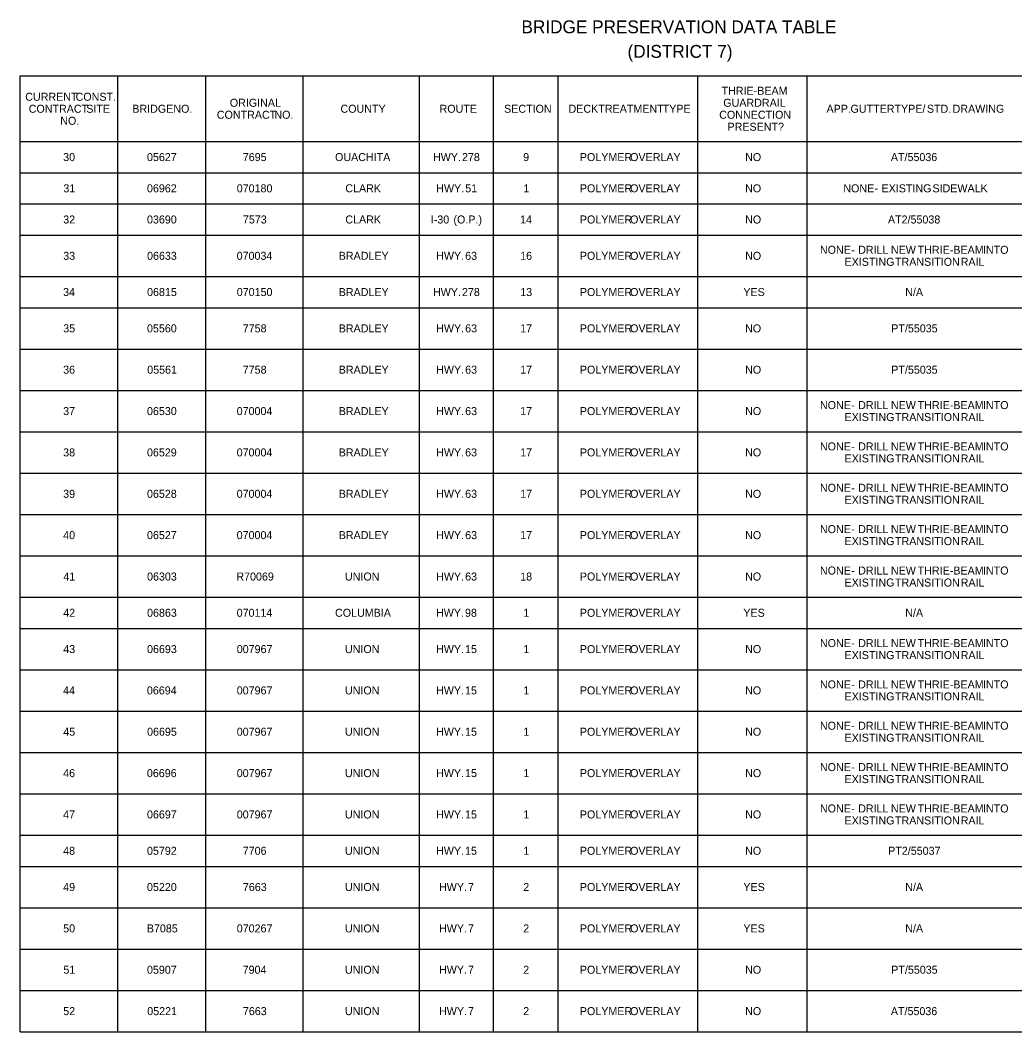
# Model space of a CAD drawing. Extents: x 16 to 1228740, y 11 to 152440.
# Drawn here: x 16.253 to 17.546, y 11.005 to 12.32 of the extents above; entities that cross this region are included whole.
import ezdxf

# ---------------------------------------------------------------- set-up
doc = ezdxf.new("R2010")
doc.units = 0
doc.layers.add('B_border', color=7, linetype='Continuous')
doc.layers.add('Default', color=7, linetype='Continuous')

msp = doc.modelspace()

# ---------------------------------------------------------------- linework, layer by layer
at = {"layer": 'B_border'}
msp.add_line((16.2529, 12.2472), (16.2529, 12.2472), dxfattribs=at)
at = {"layer": 'Default'}
for p, q in [((16.2529, 12.2472), (17.9726, 12.2472)), ((16.2529, 11.0051), (16.2529, 12.2472)), ((16.3796, 11.0051), (16.3796, 12.2472)), ((16.4942, 11.0051), (16.4942, 12.2472)), ((16.6209, 11.0051), (16.6209, 12.2472)), ((16.772, 11.0051), (16.772, 12.2472)), ((16.8684, 11.0051), (16.8684, 12.2472)), ((16.9525, 11.0051), (16.9525, 12.2472)), ((17.134, 11.0051), (17.134, 12.2472)), ((17.276, 11.0051), (17.276, 12.2472)), ((16.2529, 12.1621), (17.9726, 12.1621)), ((16.2529, 12.1215), (17.9726, 12.1215)), ((16.2529, 12.0809), (17.9726, 12.0809)), ((16.2529, 12.0404), (17.9726, 12.0404)), ((16.2529, 11.9866), (17.9726, 11.9866)), ((16.2529, 11.9461), (17.9726, 11.9461)), ((16.2529, 11.8923), (17.9726, 11.8923)), ((16.2529, 11.8386), (17.9726, 11.8386)), ((16.2529, 11.7848), (17.9726, 11.7848)), ((16.2529, 11.7311), (17.9726, 11.7311)), ((16.2529, 11.6774), (17.9726, 11.6774)), ((16.2529, 11.6236), (17.9726, 11.6236)), ((16.2529, 11.5699), (17.9726, 11.5699)), ((16.2529, 11.5293), (17.9726, 11.5293)), ((16.2529, 11.4756), (17.9726, 11.4756)), ((16.2529, 11.4218), (17.9726, 11.4218)), ((16.2529, 11.3681), (17.9726, 11.3681)), ((16.2529, 11.3143), (17.9726, 11.3143)), ((16.2529, 11.2606), (17.9726, 11.2606)), ((16.2529, 11.22), (17.9726, 11.22)), ((16.2529, 11.1663), (17.9726, 11.1663)), ((16.2529, 11.1126), (17.9726, 11.1126)), ((16.2529, 11.0588), (17.9726, 11.0588)), ((16.2529, 11.0051), (17.9726, 11.0051))]:
    msp.add_line(p, q, dxfattribs=at)

# ---------------------------------------------------------------- texts
at = {"layer": 'B_border'}
for s, p in [('BRIDGE PRESERVATION DATA TABLE ', (16.9046, 12.3027)), ('(DISTRICT 7)', (17.0425, 12.2708))]:
    msp.add_text(s, height=0.0167, rotation=360, dxfattribs=at).set_placement(p)
at = {"layer": 'Default'}
for s, p in [('CURRENT', (16.2594, 12.215)), (' CONST.', (16.321, 12.215)), ('THRIE-BEAM', (17.1648, 12.2228)), ('ORIGINAL', (16.5254, 12.2072)), ('GUARDRAIL', (17.167, 12.2072)), ('CONTRACT', (16.2639, 12.1994)), (' SITE', (16.3349, 12.1994)), ('BRIDGE', (16.3986, 12.1994)), (' NO.', (16.4481, 12.1994)), ('CONTRACT', (16.5085, 12.1916)), (' NO.', (16.5795, 12.1916)), ('COUNTY', (16.6693, 12.1994)), ('ROUTE', (16.7981, 12.1994)), ('SECTION', (16.882, 12.1994)), ('DECK', (16.9658, 12.1994)), (' TREATMENT', (17.0007, 12.1994)), (' TYPE', (17.0843, 12.1994)), ('CONNECTION', (17.1617, 12.1916)), ('APP.', (17.3012, 12.1994)), (' GUTTER', (17.3286, 12.1994)), (' TYPE/', (17.3858, 12.1994)), (' STD.', (17.4279, 12.1994)), (' DRAWING', (17.4613, 12.1994)), ('NO.', (16.3049, 12.1838)), ('PRESENT?', (17.1725, 12.176)), ('30', (16.3087, 12.1366)), ('05627', (16.4177, 12.1366)), ('7695', (16.5423, 12.1366)), ('OUACHITA', (16.6622, 12.1366)), ('HWY.', (16.7896, 12.1366)), (' 278', (16.8234, 12.1366)), ('9', (16.9068, 12.1366)), ('POLYMER', (16.9805, 12.1366)), (' OVERLAY', (17.042, 12.1366)), ('NO', (17.1954, 12.1366)), ('AT/55036', (17.3849, 12.1366)), ('31', (16.309, 12.096)), ('06962', (16.4177, 12.096)), ('070180', (16.5344, 12.096)), ('CLARK', (16.6756, 12.096)), ('HWY.', (16.7938, 12.096)), (' 51', (16.8276, 12.096)), ('1', (16.9071, 12.096)), ('POLYMER', (16.9805, 12.096)), (' OVERLAY', (17.042, 12.096)), ('NO', (17.1954, 12.096)), ('NONE', (17.3231, 12.096)), (' -', (17.3598, 12.096)), (' EXISTING', (17.3689, 12.096)), (' SIDEWALK', (17.4351, 12.096)), ('32', (16.3088, 12.0555)), ('03690', (16.4177, 12.0555)), ('7573', (16.5424, 12.0555)), ('CLARK', (16.6756, 12.0555)), ('I-30', (16.7867, 12.0555)), (' (O.P.)', (16.8123, 12.0555)), ('14', (16.9028, 12.0555)), ('POLYMER', (16.9805, 12.0555)), (' OVERLAY', (17.042, 12.0555)), ('NO', (17.1954, 12.0555)), ('AT2/55038', (17.3811, 12.0555)), ('33', (16.3088, 12.0083)), ('06633', (16.4178, 12.0083)), ('070034', (16.5343, 12.0083)), ('BRADLEY', (16.667, 12.0083)), ('HWY.', (16.7937, 12.0083)), (' 63', (16.8275, 12.0083)), ('16', (16.9029, 12.0083)), ('POLYMER', (16.9805, 12.0083)), (' OVERLAY', (17.042, 12.0083)), ('NO', (17.1954, 12.0083)), ('NONE', (17.2927, 12.0161)), (' -', (17.3295, 12.0161)), (' DRILL', (17.3385, 12.0161)), (' NEW', (17.3811, 12.0161)), (' THRIE-BEAM', (17.4159, 12.0161)), (' INTO', (17.5008, 12.0161)), ('EXISTING', (17.3247, 12.0005)), (' TRANSITION', (17.3864, 12.0005)), (' RAIL', (17.4718, 12.0005)), ('34', (16.3086, 11.9612)), ('06815', (16.4178, 11.9612)), ('070150', (16.5344, 11.9612)), ('BRADLEY', (16.667, 11.9612)), ('HWY.', (16.7896, 11.9612)), (' 278', (16.8234, 11.9612)), ('13', (16.903, 11.9612)), ('POLYMER', (16.9805, 11.9612)), (' OVERLAY', (17.042, 11.9612)), ('YES', (17.1931, 11.9612)), ('N/A', (17.4036, 11.9612)), ('35', (16.3088, 11.914)), ('05560', (16.4177, 11.914)), ('7758', (16.5422, 11.914)), ('BRADLEY', (16.667, 11.914)), ('HWY.', (16.7937, 11.914)), (' 63', (16.8275, 11.914)), ('17', (16.9029, 11.914)), ('POLYMER', (16.9805, 11.914)), (' OVERLAY', (17.042, 11.914)), ('NO', (17.1954, 11.914)), ('PT/55035', (17.3854, 11.914)), ('36', (16.3087, 11.8603)), ('05561', (16.418, 11.8603)), ('7758', (16.5422, 11.8603)), ('BRADLEY', (16.667, 11.8603)), ('HWY.', (16.7937, 11.8603)), (' 63', (16.8275, 11.8603)), ('17', (16.9029, 11.8603)), ('POLYMER', (16.9805, 11.8603)), (' OVERLAY', (17.042, 11.8603)), ('NO', (17.1954, 11.8603)), ('PT/55035', (17.3854, 11.8603)), ('NONE', (17.2927, 11.8143)), (' -', (17.3295, 11.8143)), (' DRILL', (17.3385, 11.8143)), (' NEW', (17.3811, 11.8143)), (' THRIE-BEAM', (17.4159, 11.8143)), (' INTO', (17.5008, 11.8143)), ('37', (16.3087, 11.8065)), ('06530', (16.4177, 11.8065)), ('070004', (16.5343, 11.8065)), ('BRADLEY', (16.667, 11.8065)), ('HWY.', (16.7937, 11.8065)), (' 63', (16.8275, 11.8065)), ('17', (16.9029, 11.8065)), ('POLYMER', (16.9805, 11.8065)), (' OVERLAY', (17.042, 11.8065)), ('NO', (17.1954, 11.8065)), ('EXISTING', (17.3247, 11.7987)), (' TRANSITION', (17.3864, 11.7987)), (' RAIL', (17.4718, 11.7987)), ('NONE', (17.2927, 11.7606)), (' DRILL', (17.3385, 11.7606)), (' NEW', (17.3811, 11.7606)), (' THRIE-BEAM', (17.4159, 11.7606)), (' INTO', (17.5008, 11.7606)), ('38', (16.3087, 11.7528)), ('06529', (16.4177, 11.7528)), ('070004', (16.5343, 11.7528)), ('BRADLEY', (16.667, 11.7528)), ('HWY.', (16.7937, 11.7528)), (' 63', (16.8275, 11.7528)), ('17', (16.9029, 11.7528)), ('POLYMER', (16.9805, 11.7528)), (' OVERLAY', (17.042, 11.7528)), ('NO', (17.1954, 11.7528)), ('EXISTING', (17.3247, 11.745)), (' -', (17.3295, 11.7606)), (' TRANSITION', (17.3864, 11.745)), (' RAIL', (17.4718, 11.745)), ('NONE', (17.2927, 11.7068)), (' DRILL', (17.3385, 11.7068)), (' NEW', (17.3811, 11.7068)), (' THRIE-BEAM', (17.4159, 11.7068)), (' INTO', (17.5008, 11.7068)), ('39', (16.3087, 11.699)), ('06528', (16.4177, 11.699)), ('070004', (16.5343, 11.699)), ('BRADLEY', (16.667, 11.699)), ('HWY.', (16.7937, 11.699)), (' 63', (16.8275, 11.699)), ('17', (16.9029, 11.699)), ('POLYMER', (16.9805, 11.699)), (' OVERLAY', (17.042, 11.699)), ('NO', (17.1954, 11.699)), ('EXISTING', (17.3247, 11.6912)), (' -', (17.3295, 11.7068)), (' TRANSITION', (17.3864, 11.6912)), (' RAIL', (17.4718, 11.6912)), ('NONE', (17.2927, 11.6531)), (' DRILL', (17.3385, 11.6531)), (' NEW', (17.3811, 11.6531)), (' THRIE-BEAM', (17.4159, 11.6531)), (' INTO', (17.5008, 11.6531)), ('40', (16.3087, 11.6453)), ('06527', (16.4177, 11.6453)), ('070004', (16.5343, 11.6453)), ('BRADLEY', (16.667, 11.6453)), ('HWY.', (16.7937, 11.6453)), (' 63', (16.8275, 11.6453)), ('17', (16.9029, 11.6453)), ('POLYMER', (16.9805, 11.6453)), (' OVERLAY', (17.042, 11.6453)), ('NO', (17.1954, 11.6453)), ('EXISTING', (17.3247, 11.6375)), (' -', (17.3295, 11.6531)), (' TRANSITION', (17.3864, 11.6375)), (' RAIL', (17.4718, 11.6375)), ('NONE', (17.2927, 11.5993)), (' DRILL', (17.3385, 11.5993)), (' NEW', (17.3811, 11.5993)), (' THRIE-BEAM', (17.4159, 11.5993)), (' INTO', (17.5008, 11.5993)), ('41', (16.309, 11.5915)), ('06303', (16.4178, 11.5915)), ('R70069', (16.5339, 11.5915)), ('UNION', (16.6751, 11.5915)), ('HWY.', (16.7937, 11.5915)), (' 63', (16.8275, 11.5915)), ('18', (16.9029, 11.5915)), ('POLYMER', (16.9805, 11.5915)), (' OVERLAY', (17.042, 11.5915)), ('NO', (17.1954, 11.5915)), (' -', (17.3295, 11.5993)), ('EXISTING', (17.3247, 11.5837)), (' TRANSITION', (17.3864, 11.5837)), (' RAIL', (17.4718, 11.5837)), ('N/A', (17.4036, 11.5444)), ('42', (16.3088, 11.5444)), ('06863', (16.4178, 11.5444)), ('070114', (16.5343, 11.5444)), ('COLUMBIA', (16.6622, 11.5444)), ('HWY.', (16.7935, 11.5444)), (' 98', (16.8273, 11.5444)), ('1', (16.9071, 11.5444)), ('POLYMER', (16.9805, 11.5444)), (' OVERLAY', (17.042, 11.5444)), ('YES', (17.1931, 11.5444)), ('43', (16.3088, 11.4972)), ('06693', (16.4178, 11.4972)), ('007967', (16.5344, 11.4972)), ('UNION', (16.6751, 11.4972)), ('HWY.', (16.7936, 11.4972)), (' 15', (16.8274, 11.4972)), ('1', (16.9071, 11.4972)), ('POLYMER', (16.9805, 11.4972)), (' OVERLAY', (17.042, 11.4972)), ('NO', (17.1954, 11.4972)), ('NONE', (17.2927, 11.505)), (' -', (17.3295, 11.505)), (' DRILL', (17.3385, 11.505)), (' NEW', (17.3811, 11.505)), (' THRIE-BEAM', (17.4159, 11.505)), (' INTO', (17.5008, 11.505)), ('EXISTING', (17.3247, 11.4894)), (' TRANSITION', (17.3864, 11.4894)), (' RAIL', (17.4718, 11.4894)), ('44', (16.3086, 11.4435)), ('06694', (16.4176, 11.4435)), ('007967', (16.5344, 11.4435)), ('UNION', (16.6751, 11.4435)), ('HWY.', (16.7936, 11.4435)), (' 15', (16.8274, 11.4435)), ('1', (16.9071, 11.4435)), ('POLYMER', (16.9805, 11.4435)), (' OVERLAY', (17.042, 11.4435)), ('NO', (17.1954, 11.4435)), ('NONE', (17.2927, 11.4513)), (' -', (17.3295, 11.4513)), (' DRILL', (17.3385, 11.4513)), (' NEW', (17.3811, 11.4513)), (' THRIE-BEAM', (17.4159, 11.4513)), (' INTO', (17.5008, 11.4513)), ('EXISTING', (17.3247, 11.4357)), (' TRANSITION', (17.3864, 11.4357)), (' RAIL', (17.4718, 11.4357)), ('45', (16.3088, 11.3898)), ('06695', (16.4178, 11.3898)), ('007967', (16.5344, 11.3898)), ('UNION', (16.6751, 11.3898)), ('HWY.', (16.7936, 11.3898)), (' 15', (16.8274, 11.3898)), ('1', (16.9071, 11.3898)), ('POLYMER', (16.9805, 11.3898)), (' OVERLAY', (17.042, 11.3898)), ('NO', (17.1954, 11.3898)), ('NONE', (17.2927, 11.3976)), (' -', (17.3295, 11.3976)), (' DRILL', (17.3385, 11.3976)), (' NEW', (17.3811, 11.3976)), (' THRIE-BEAM', (17.4159, 11.3976)), (' INTO', (17.5008, 11.3976)), ('EXISTING', (17.3247, 11.382)), (' TRANSITION', (17.3864, 11.382)), (' RAIL', (17.4718, 11.382)), ('46', (16.3087, 11.336)), ('06696', (16.4176, 11.336)), ('007967', (16.5344, 11.336)), ('UNION', (16.6751, 11.336)), ('HWY.', (16.7936, 11.336)), (' 15', (16.8274, 11.336)), ('1', (16.9071, 11.336)), ('POLYMER', (16.9805, 11.336)), (' OVERLAY', (17.042, 11.336)), ('NO', (17.1954, 11.336)), ('NONE', (17.2927, 11.3438)), (' -', (17.3295, 11.3438)), (' DRILL', (17.3385, 11.3438)), (' NEW', (17.3811, 11.3438)), (' THRIE-BEAM', (17.4159, 11.3438)), (' INTO', (17.5008, 11.3438)), ('EXISTING', (17.3247, 11.3282)), (' TRANSITION', (17.3864, 11.3282)), (' RAIL', (17.4718, 11.3282)), ('47', (16.3087, 11.2823)), ('06697', (16.4177, 11.2823)), ('007967', (16.5344, 11.2823)), ('UNION', (16.6751, 11.2823)), ('HWY.', (16.7936, 11.2823)), (' 15', (16.8274, 11.2823)), ('1', (16.9071, 11.2823)), ('POLYMER', (16.9805, 11.2823)), (' OVERLAY', (17.042, 11.2823)), ('NO', (17.1954, 11.2823)), ('NONE', (17.2927, 11.2901)), (' -', (17.3295, 11.2901)), (' DRILL', (17.3385, 11.2901)), (' NEW', (17.3811, 11.2901)), (' THRIE-BEAM', (17.4159, 11.2901)), (' INTO', (17.5008, 11.2901)), ('EXISTING', (17.3247, 11.2745)), (' TRANSITION', (17.3864, 11.2745)), (' RAIL', (17.4718, 11.2745)), ('48', (16.3087, 11.2351)), ('05792', (16.4177, 11.2351)), ('7706', (16.5422, 11.2351)), ('UNION', (16.6751, 11.2351)), ('HWY.', (16.7936, 11.2351)), (' 15', (16.8274, 11.2351)), ('1', (16.9071, 11.2351)), ('POLYMER', (16.9805, 11.2351)), (' OVERLAY', (17.042, 11.2351)), ('NO', (17.1954, 11.2351)), ('PT2/55037', (17.3814, 11.2351)), ('49', (16.3087, 11.188)), ('05220', (16.4177, 11.188)), ('7663', (16.5424, 11.188)), ('UNION', (16.6751, 11.188)), ('HWY.', (16.7974, 11.188)), (' 7', (16.8312, 11.188)), ('2', (16.9069, 11.188)), ('POLYMER', (16.9805, 11.188)), (' OVERLAY', (17.042, 11.188)), ('YES', (17.1931, 11.188)), ('N/A', (17.4036, 11.188)), ('50', (16.3087, 11.1342)), ('B7085', (16.4175, 11.1342)), ('070267', (16.5344, 11.1342)), ('UNION', (16.6751, 11.1342)), ('HWY.', (16.7974, 11.1342)), (' 7', (16.8312, 11.1342)), ('2', (16.9069, 11.1342)), ('POLYMER', (16.9805, 11.1342)), (' OVERLAY', (17.042, 11.1342)), ('YES', (17.1931, 11.1342)), ('N/A', (17.4036, 11.1342)), ('51', (16.309, 11.0805)), ('05907', (16.4177, 11.0805)), ('7904', (16.5421, 11.0805)), ('UNION', (16.6751, 11.0805)), ('HWY.', (16.7974, 11.0805)), (' 7', (16.8312, 11.0805)), ('2', (16.9069, 11.0805)), ('POLYMER', (16.9805, 11.0805)), (' OVERLAY', (17.042, 11.0805)), ('NO', (17.1954, 11.0805)), ('PT/55035', (17.3854, 11.0805)), ('52', (16.3088, 11.0267)), ('05221', (16.418, 11.0267)), ('7663', (16.5424, 11.0267)), ('UNION', (16.6751, 11.0267)), ('HWY.', (16.7974, 11.0267)), (' 7', (16.8312, 11.0267)), ('2', (16.9069, 11.0267)), ('POLYMER', (16.9805, 11.0267)), (' OVERLAY', (17.042, 11.0267)), ('NO', (17.1954, 11.0267)), ('AT/55036', (17.3849, 11.0267))]:
    msp.add_text(s, height=0.0104, dxfattribs=at).set_placement(p)

doc.saveas('drawing.dxf')
